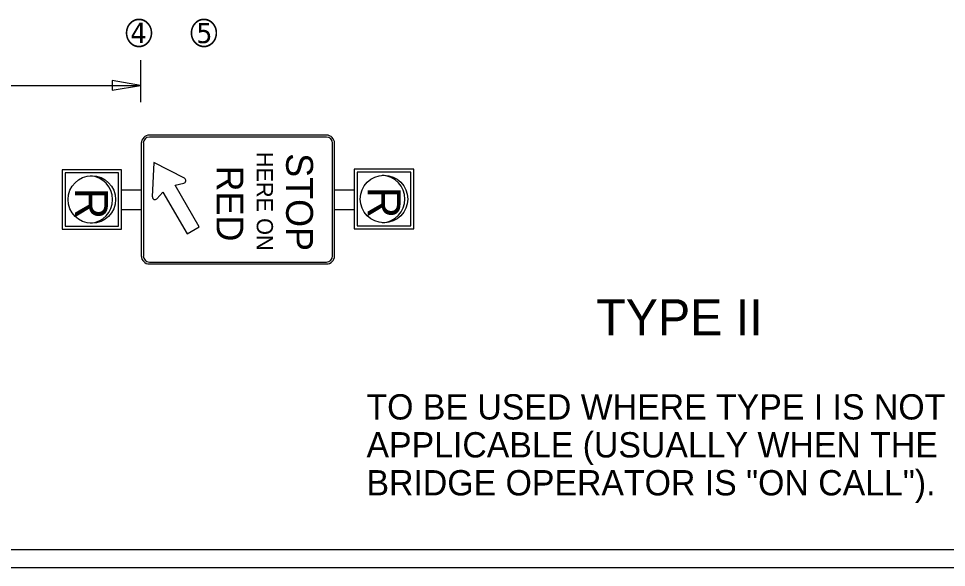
# Model space of a CAD drawing. Extents: x 15 to 764, y 7 to 487.
# Drawn here: x 477.5 to 605.9, y 311.5 to 387.4 of the extents above; entities that cross this region are included whole.
import ezdxf

# ---------------------------------------------------------------- set-up
doc = ezdxf.new("R2010")
doc.units = 0
for name, color, linetype in [('Default', 7, 'Continuous'), ('Dimension', 7, 'Continuous'), ('TextStructures', 7, 'Continuous')]:
    doc.layers.add(name, color=color, linetype=linetype)

msp = doc.modelspace()

# ---------------------------------------------------------------- linework, layer by layer
at = {"layer": 'Default'}
for p, q in [((494.33, 381.66), (494.33, 375.84)), ((408.43, 378.17), (494.33, 378.17)), ((520.09, 371.28), (495.57, 371.28)), ((494.46, 370.17), (494.46, 354.56)), ((494.74, 370.17), (494.74, 354.56)), ((520.09, 371), (495.57, 371)), ((520.93, 354.56), (520.93, 370.17)), ((521.21, 354.56), (521.21, 370.17)), ((496.2, 367.5), (495.98, 362.75)), ((500.42, 365.31), (496.2, 367.5)), ((483.5, 366.48), (483.5, 358.26)), ((491.72, 366.48), (483.5, 366.48)), ((483.91, 366.07), (483.91, 358.67)), ((491.31, 366.07), (483.91, 366.07)), ((491.31, 358.67), (491.31, 366.07)), ((491.72, 358.26), (491.72, 366.48)), ((523.93, 366.55), (523.93, 358.33)), ((532.15, 366.55), (523.93, 366.55)), ((524.34, 366.14), (524.34, 358.74)), ((531.74, 366.14), (524.34, 366.14)), ((531.74, 358.74), (531.74, 366.14)), ((532.15, 358.33), (532.15, 366.55)), ((491.74, 363.72), (494.46, 363.72)), ((499.14, 364.35), (500.34, 364.63)), ((502.47, 358.58), (499.14, 364.35)), ((521.21, 363.72), (523.93, 363.72)), ((496.61, 362.48), (497.45, 363.38)), ((497.45, 363.38), (500.79, 357.6)), ((491.74, 361), (494.46, 361)), ((521.21, 361), (523.93, 361)), ((483.5, 358.26), (491.72, 358.26)), ((483.91, 358.67), (491.31, 358.67)), ((500.79, 357.6), (502.47, 358.58)), ((523.93, 358.33), (532.15, 358.33)), ((524.34, 358.74), (531.74, 358.74)), ((495.57, 353.72), (520.09, 353.72)), ((495.57, 353.45), (520.09, 353.45))]:
    msp.add_line(p, q, dxfattribs=at)
for centre, radius, start, end in [((495.57, 370.17), 1.11, 90, 180), ((520.09, 370.17), 1.11, 0, 90), ((495.57, 370.17), 0.836, 90, 180), ((520.09, 370.17), 0.836, 0, 90), ((487.2, 362.37), 3.29, 273.5833, 86.4167), ((500.25, 364.98), 0.366, 283.0563, 62.5967), ((527.63, 362.44), 3.29, 273.5833, 86.4167), ((496.35, 362.73), 0.366, 177.4033, 316.9437), ((495.57, 354.56), 1.11, 180, 270), ((495.57, 354.56), 0.836, 180, 270), ((520.09, 354.56), 1.11, 270, 360), ((520.09, 354.56), 0.836, 270, 360)]:
    msp.add_arc(centre, radius, start, end, dxfattribs=at)
at = {"layer": 'Dimension'}
msp.add_lwpolyline([(494.33, 378.17), (490.42, 378.84), (490.42, 377.51)], close=True, dxfattribs=at)
at = {"layer": 'TextStructures'}
for p, q in [((446.19, 313.96), (764.08, 313.96)), ((446.19, 311.46), (764.08, 311.46))]:
    msp.add_line(p, q, dxfattribs=at)
for centre in [(487.61, 362.37), (528.04, 362.44)]:
    msp.add_circle(centre, 3.29, dxfattribs=at)

# ---------------------------------------------------------------- texts
at = {"layer": 'Default'}
for s, height, p in [('HERE ON', 2.247, (510.43, 368.98)), ('STOP', 3.718, (514.5, 368.78)), ('RED', 3.718, (504.87, 367.07))]:
    msp.add_text(s, height=height, rotation=270, dxfattribs=at).set_placement(p)
at = {"layer": 'TextStructures'}
for s, p in [('➃', (492.29, 383.67)), ('➄', (501.27, 383.67))]:
    msp.add_text(s, height=3.5, dxfattribs=at).set_placement(p)
for s, height, rotation, p in [('R', 4.54, 270, (485.3, 364.02)), ('R', 4.54, 270, (525.79, 364.16)), ('TYPE II ', 5, 0.0007, (557.41, 343.57)), ('TO BE USED WHERE TYPE I IS NOT ', 3.5, 0.0007, (525.62, 331.93)), ('APPLICABLE (USUALLY WHEN THE ', 3.5, 0.0007, (525.62, 326.68)), ('BRIDGE OPERATOR IS "ON CALL").', 3.5, 0.0007, (525.62, 321.43))]:
    msp.add_text(s, height=height, rotation=rotation, dxfattribs=at).set_placement(p)

doc.saveas('drawing.dxf')
